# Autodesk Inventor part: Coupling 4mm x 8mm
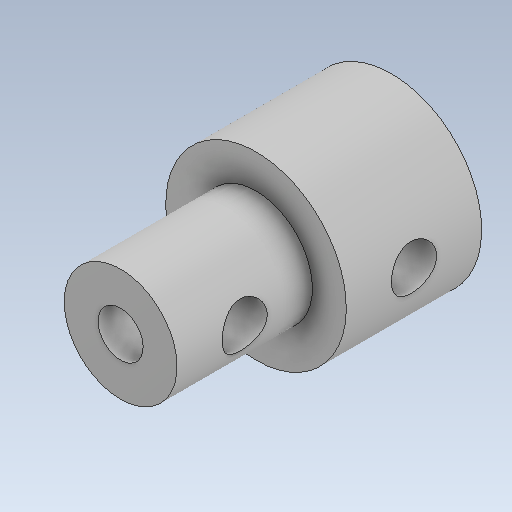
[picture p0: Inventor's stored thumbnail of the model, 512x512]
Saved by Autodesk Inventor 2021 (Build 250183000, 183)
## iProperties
Created: 2026-10
Part Number: Coupling 4mm x 8mm
Material: Steel
Document SubType Name: Modeling
Designer: hp
Density: 7.85 g/cm^3
Appearance: Default
Author: hp
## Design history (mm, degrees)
feature "Body1"
body "Solid1"
